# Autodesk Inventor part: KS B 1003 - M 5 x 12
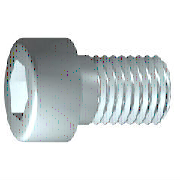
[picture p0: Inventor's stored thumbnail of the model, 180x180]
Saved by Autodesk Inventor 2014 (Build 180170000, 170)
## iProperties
IsCustomPart: 0
Created: 2009-02
Part Number: KS B 1003 - M 5 x 12
Material: 강, 연강
Description: 6각머리 태핑 나사
Document SubType Name: Modeling
Standard: KS B 1003
Designer: KYOUNG IL JANG
Standards Organization: KS
Language: ko-KR
Size Designation: M 5 x 12
Categories: <MemberInstance><Categories><Category DisplayName="조임쇠" InternalName="e4da775c-781d-43d5-af7c-5136215cf5a6" Mnemonic="FSTN"><Category DisplayName="볼트" InternalN
Density: 7.86 g/cm^3
Appearance: 강철
Mass: 3.72825 g
Surface Area: 4.62573 cm^2
Volume: 0.474332 cm^3
Author: KYOUNG IL JANG
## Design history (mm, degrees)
sketch "스케치1"
  geometry: L1 (-1.167, 0)-(12, 0); L2 (12, 0)-(12, 2.5); L3 (12, 2.5)-(2, 2.5); L4 (2, 2.5)-(1.509, 2.5); L5 (1.509, 2.5)-(0, 2.5); L6 (0, 2.5)-(0, 4.25); L7 (0, 4.25)-(-5, 4.25); L8 (-5, 4.25)-(-5, 2.309); L9 (-5, 2.309)-(-2.5, 2.309); L10 (-2.5, 2.309)-(-1.167, 0); L11 (-8.4, 0)-(15.4, 0) reference; L12 (0, -0.85)-(0, 5.1) reference; L13 (2, 2.5)-(0, 2.5)
  constraints: 22 end point, 6 parallel, 2 collinear, 2 perpendicular, 1 horizontal, 1 point on line
  dimensions: "d1" = 10 distance from line of L3.end L2 (= GEL); "d2" = 0.49086 distance of L4.end L3.end (computed from GAL); "d3" = 5 distance between parallel lines of L8 L6 (= KOH); "d4" = 2.5 distance of L8.end L9.end (= INTI); "d5" = 60 deg angle of L10 L1; "d6" = 5 diameter of L3 L1 (= GD); "d7" = 5 diameter of L5 L1 (= BDM); "d8" = 4.6188 diameter of L9 L1 (= 1.1547 x SW); "d9" = 8.5 diameter of L7 L1 (= KOD); "d26" = 12 distance between parallel lines of L12 L2 (= NLG)
revolve "본체" sketch "스케치1" stored, may be unused: angle "d10" = 90 deg
sketch "스케치2"
  geometry: L1 (0, -5.95)-(0, 5.95) reference; L2 (-5.95, 0)-(5.95, 0) reference; L3 (2.309, 0)-(1.155, -2); L4 (1.155, -2)-(-1.155, -2); L5 (-1.155, -2)-(-2.309, 0); L6 (-2.309, 0)-(-1.155, 2); L7 (-1.155, 2)-(1.155, 2); L8 (1.155, 2)-(2.309, 0); 2 further points
  constraints: 12 end point, 1 coincident, 1 horizontal alignment, 1 point on line, 12 other
extrude "슬롯" join sketch "스케치2" stored distance "d11" = 10; taper "d12" = 0 deg
workplane "Work Plane1"
fillet "Fillet2" dims "d30" = 0.1 (= R)
body "Solid1"
fillet "모깎기1" dims "d17" = 0.5 (= RR)
feature "스레드" dims "d13" = 10 (= GEL), "d14" = 0
chamfer "모따기1" distance "d15" = 0.49076 (= -0.5 x SPD + 0.5 x GD); stored, may be unused: second distance "d16" = 0.49076 (= GUL), angle "d27" = 45 deg
other parameters: "GD" = 5 (= NND) [user parameter; used in 2 equation terms], "NLG" = 12 [user parameter; used in 1 equation term], "GEL" = 10 [user parameter; used in 2 equation terms], "KOD" = 8.5 [user parameter; used in 1 equation term], "KOH" = 5 [user parameter; used in 1 equation term], "INTI" = 2.5 [user parameter; used in 1 equation term], "GAL" = 0.49076 (= 0.61345 x PTC) [user parameter; used in 1 equation term], "GUL" = 0.49076 (= 0.61345 x PTC) [user parameter; used in 1 equation term], "BDM" = 5 (= NND) [user parameter; used in 1 equation term], "SW" = 4 [user parameter; used in 2 equation terms], "RR" = 0.5 [user parameter; used in 1 equation term], "SPD" = 4.01848 (= NND - 1.2269 x PTC) [user parameter; used in 1 equation term], "d19" = 0, "d28" = 0, "d29" = 0, "R" = 0.1 [user parameter; used in 1 equation term], "PHH" = 0.2 [user parameter], "GD1" = 4.01848 (= THREADDIA - 1.2269 x PTC) [user parameter], "THREADDIA" = 5 [user parameter; used in 1 equation term], "FAWI" = 45 deg [user parameter], "TPU" = 12.5 (computed from PTC) [user parameter], "PTC" = 0.8 [user parameter; used in 5 equation terms], "NND" = 5 [user parameter; used in 3 equation terms], "TOA" = 30 deg [user parameter], "E0" = 4.62 (= 1.155 x SW) [user parameter]
